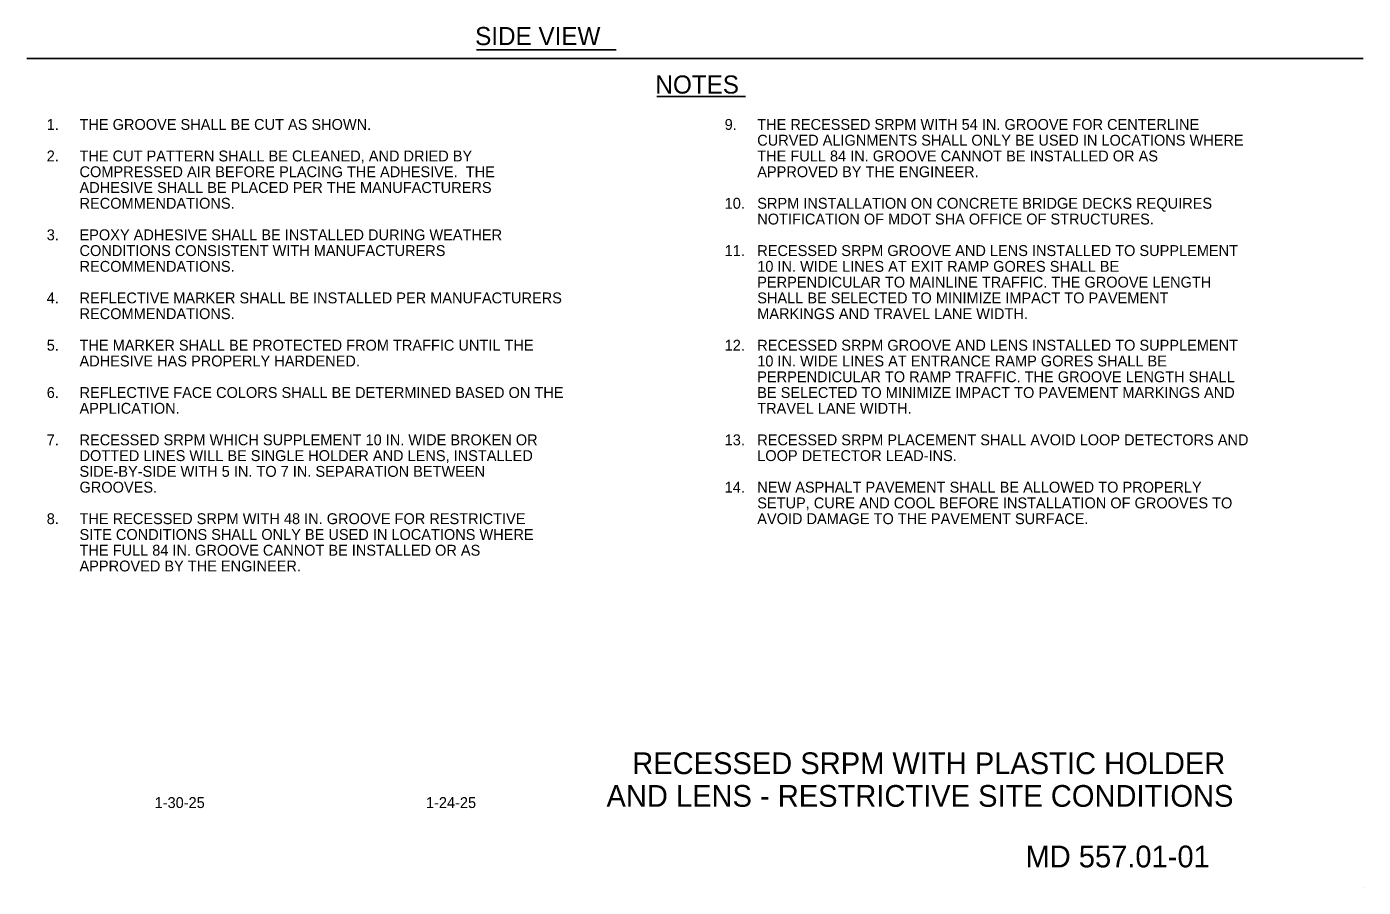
# Model space of a CAD drawing. Extents: x 12.2 to 19.6, y 5.9 to 16.3.
# Drawn here: x 12.25 to 19.62, y 5.94 to 10.68 of the extents above; entities that cross this region are included whole.
import ezdxf

# ---------------------------------------------------------------- set-up
doc = ezdxf.new("R2010")
doc.units = 0
for name, color, linetype in [('BORD-LINE', 7, 'Continuous'), ('DETL-LINE', 7, 'Continuous'), ('DETL-NOTE', 7, 'Continuous'), ('DETL-TITL', 7, 'Continuous'), ('TTLB-TEXT', 7, 'Continuous')]:
    doc.layers.add(name, color=color, linetype=linetype)

msp = doc.modelspace()

# ---------------------------------------------------------------- linework, layer by layer
at = {"layer": 'BORD-LINE'}
msp.add_line((12.2466, 10.5087), (19.6208, 10.5087), dxfattribs=at)
at = {"layer": 'DETL-LINE'}
msp.add_line((15.7243, 10.2992), (16.2128, 10.2992), dxfattribs=at)
at = {"layer": 'DETL-TITL'}
msp.add_line((14.7291, 10.5564), (15.4985, 10.5564), dxfattribs=at)
at = {"layer": 'TTLB-TEXT'}
msp.add_line((19.6215, 5.9375), (19.6215, 5.9375), dxfattribs=at)

# ---------------------------------------------------------------- texts
at = {"layer": 'DETL-NOTE'}
for s, height, p in [('NOTES', 0.1, (15.716, 10.3159)), ('1. ', 0.06, (12.357, 10.1157)), ('THE GROOVE SHALL BE CUT AS SHOWN.', 0.06, (12.5379, 10.1157)), ('9.', 0.06, (16.0978, 10.1157)), ('THE RECESSED SRPM WITH 54 IN. GROOVE FOR CENTERLINE ', 0.06, (16.2775, 10.1157)), ('CURVED ALIGNMENTS SHALL ONLY BE USED IN LOCATIONS WHERE ', 0.06, (16.2775, 10.0287)), ('2. ', 0.06, (12.357, 9.9417)), ('THE CUT PATTERN SHALL BE CLEANED, AND DRIED BY ', 0.06, (12.5379, 9.9417)), ('THE FULL 84 IN. GROOVE CANNOT BE INSTALLED OR AS ', 0.06, (16.2775, 9.9417)), ('COMPRESSED AIR BEFORE PLACING THE ADHESIVE.  THE ', 0.06, (12.5379, 9.8547)), ('APPROVED BY THE ENGINEER.', 0.06, (16.2775, 9.8547)), ('ADHESIVE SHALL BE PLACED PER THE MANUFACTURERS ', 0.06, (12.5379, 9.7677)), ('RECOMMENDATIONS.', 0.06, (12.5379, 9.6807)), ('10.', 0.06, (16.0978, 9.6807)), ('SRPM INSTALLATION ON CONCRETE BRIDGE DECKS REQUIRES ', 0.06, (16.2775, 9.6807)), ('NOTIFICATION OF MDOT SHA OFFICE OF STRUCTURES.', 0.06, (16.2775, 9.5937)), ('3. ', 0.06, (12.357, 9.5067)), ('EPOXY ADHESIVE SHALL BE INSTALLED DURING WEATHER ', 0.06, (12.5379, 9.5067)), ('CONDITIONS CONSISTENT WITH MANUFACTURERS ', 0.06, (12.5379, 9.4197)), ('11.', 0.06, (16.0978, 9.4197)), ('RECESSED SRPM GROOVE AND LENS INSTALLED TO SUPPLEMENT ', 0.06, (16.2775, 9.4197)), ('RECOMMENDATIONS. ', 0.06, (12.5379, 9.3327)), ('10 IN. WIDE LINES AT EXIT RAMP GORES SHALL BE ', 0.06, (16.2775, 9.3327)), ('PERPENDICULAR TO MAINLINE TRAFFIC. THE GROOVE LENGTH ', 0.06, (16.2775, 9.2457)), ('4. ', 0.06, (12.357, 9.1587)), ('REFLECTIVE MARKER SHALL BE INSTALLED PER MANUFACTURERS ', 0.06, (12.5379, 9.1587)), ('SHALL BE SELECTED TO MINIMIZE IMPACT TO PAVEMENT ', 0.06, (16.2775, 9.1587)), ('RECOMMENDATIONS.', 0.06, (12.5379, 9.0717)), ('MARKINGS AND TRAVEL LANE WIDTH.', 0.06, (16.2775, 9.0717)), ('5. ', 0.06, (12.357, 8.8977)), ('THE MARKER SHALL BE PROTECTED FROM TRAFFIC UNTIL THE ', 0.06, (12.5379, 8.8977)), ('12.', 0.06, (16.0978, 8.8977)), ('RECESSED SRPM GROOVE AND LENS INSTALLED TO SUPPLEMENT ', 0.06, (16.2775, 8.8977)), ('ADHESIVE HAS PROPERLY HARDENED.', 0.06, (12.5379, 8.8107)), ('10 IN. WIDE LINES AT ENTRANCE RAMP GORES SHALL BE ', 0.06, (16.2775, 8.8107)), ('PERPENDICULAR TO RAMP TRAFFIC. THE GROOVE LENGTH SHALL ', 0.06, (16.2775, 8.7237)), ('6. ', 0.06, (12.357, 8.6367)), ('REFLECTIVE FACE COLORS SHALL BE DETERMINED BASED ON THE ', 0.06, (12.5379, 8.6367)), ('BE SELECTED TO MINIMIZE IMPACT TO PAVEMENT MARKINGS AND ', 0.06, (16.2775, 8.6367)), ('APPLICATION.', 0.06, (12.5379, 8.5497)), ('TRAVEL LANE WIDTH.', 0.06, (16.2775, 8.5497)), ('7.', 0.06, (12.357, 8.3757)), ('RECESSED SRPM WHICH SUPPLEMENT 10 IN. WIDE BROKEN OR ', 0.06, (12.5379, 8.3757)), ('13.', 0.06, (16.0978, 8.3757)), ('RECESSED SRPM PLACEMENT SHALL AVOID LOOP DETECTORS AND ', 0.06, (16.2775, 8.3757)), ('DOTTED LINES WILL BE SINGLE HOLDER AND LENS, INSTALLED ', 0.06, (12.5379, 8.2887)), ('LOOP DETECTOR LEAD-INS.', 0.06, (16.2775, 8.2887)), ('SIDE-BY-SIDE WITH 5 IN. TO 7 IN. SEPARATION BETWEEN ', 0.06, (12.5379, 8.2017)), ('GROOVES.', 0.06, (12.5379, 8.1147)), ('14.', 0.06, (16.0978, 8.1147)), ('NEW ASPHALT PAVEMENT SHALL BE ALLOWED TO PROPERLY ', 0.06, (16.2775, 8.1147)), ('SETUP, CURE AND COOL BEFORE INSTALLATION OF GROOVES TO ', 0.06, (16.2775, 8.0277)), ('8.', 0.06, (12.357, 7.9407)), ('THE RECESSED SRPM WITH 48 IN. GROOVE FOR RESTRICTIVE ', 0.06, (12.5379, 7.9407)), ('AVOID DAMAGE TO THE PAVEMENT SURFACE.', 0.06, (16.2775, 7.9407)), ('SITE CONDITIONS SHALL ONLY BE USED IN LOCATIONS WHERE ', 0.06, (12.5379, 7.8537)), ('THE FULL 84 IN. GROOVE CANNOT BE INSTALLED OR AS ', 0.06, (12.5379, 7.7667)), ('APPROVED BY THE ENGINEER.', 0.06, (12.5379, 7.6797))]:
    msp.add_text(s, height=height, dxfattribs=at).set_placement(p)
at = {"layer": 'DETL-TITL'}
msp.add_text('SIDE VIEW', height=0.1, dxfattribs=at).set_placement((14.721, 10.5832))
at = {"layer": 'TTLB-TEXT'}
for s, height, p in [('RECESSED SRPM WITH PLASTIC HOLDER ', 0.12, (15.5879, 6.5615)), ('AND LENS - RESTRICTIVE SITE CONDITIONS', 0.12, (15.4456, 6.3815)), ('1-30-25', 0.06, (12.9523, 6.3746)), ('1-24-25', 0.06, (14.4496, 6.3746)), ('MD 557.01-01', 0.12, (17.7577, 6.0472))]:
    msp.add_text(s, height=height, dxfattribs=at).set_placement(p)

doc.saveas('drawing.dxf')
